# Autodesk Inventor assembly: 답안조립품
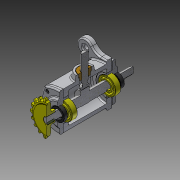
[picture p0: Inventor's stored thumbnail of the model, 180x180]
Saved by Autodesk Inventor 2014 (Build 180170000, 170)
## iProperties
Created: 2016-05
Part Number: 답안조립품
Document SubType Name: Assembly
Designer: Administrator
Author: Administrator
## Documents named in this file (12)
- C:\Users\Administrator\Desktop\460507V1024\답안조립품.iam
- C:\Users\Administrator\Desktop\460507V1024\본체.ipt
- C:\Users\Administrator\Desktop\460507V1024\M4x0.7x12.ipt
- C:\Users\Administrator\Desktop\460507V1024\베어링-6203.ipt
- C:\Users\Administrator\Desktop\460507V1024\부시.ipt
- C:\Users\Administrator\Desktop\460507V1024\스퍼기어.ipt
- C:\Users\Administrator\Desktop\460507V1024\스프로킷.ipt
- C:\Users\Administrator\Desktop\460507V1024\슬라이더.ipt
- C:\Users\Administrator\Desktop\460507V1024\오일실.ipt
- C:\Users\Administrator\Desktop\460507V1024\커버.ipt
- C:\Users\Administrator\Desktop\460507V1024\키5x5.ipt
- C:\Users\Administrator\Desktop\460507V1024\편심축.ipt
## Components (8 placed, 1 different names)
1. M4x0.7x12:1
2. M4x0.7x12:3
3. M4x0.7x12:4
4. M4x0.7x12:5
5. M4x0.7x12:2
6. M4x0.7x12:6
7. M4x0.7x12:7
8. M4x0.7x12:8
